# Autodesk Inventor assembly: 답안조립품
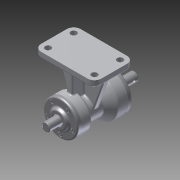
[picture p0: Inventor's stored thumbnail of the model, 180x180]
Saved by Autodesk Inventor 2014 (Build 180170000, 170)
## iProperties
Created: 2015-08
Part Number: 답안조립품
Document SubType Name: Assembly
Designer: SEC
Author: SEC
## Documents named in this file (10)
- C:\Users\SEC\Desktop\450805V1001\답안조립품.iam
- C:\Users\SEC\Desktop\450805V1001\축.ipt
- C:\Users\SEC\Desktop\450805V1001\베어링 6203.ipt
- C:\Users\SEC\Desktop\450805V1001\베어링 6205.ipt
- C:\Users\SEC\Desktop\450805V1001\본체.ipt
- C:\Users\SEC\Desktop\450805V1001\앞커버.ipt
- C:\Users\SEC\Desktop\450805V1001\뒤커버.ipt
- C:\Users\SEC\Desktop\450805V1001\오일실 .ipt
- 오일실 .ipt
- C:\Users\SEC\Desktop\450805V1001\M4x0.5.ipt
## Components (10 placed, 1 different names)
1. M4x0.5:1
2. M4x0.5:2
3. M4x0.5:3
4. M4x0.5:4
5. M4x0.5:5
6. M4x0.5:6
7. M4x0.5:7
8. M4x0.5:8
9. M4x0.5:9
10. M4x0.5:10
